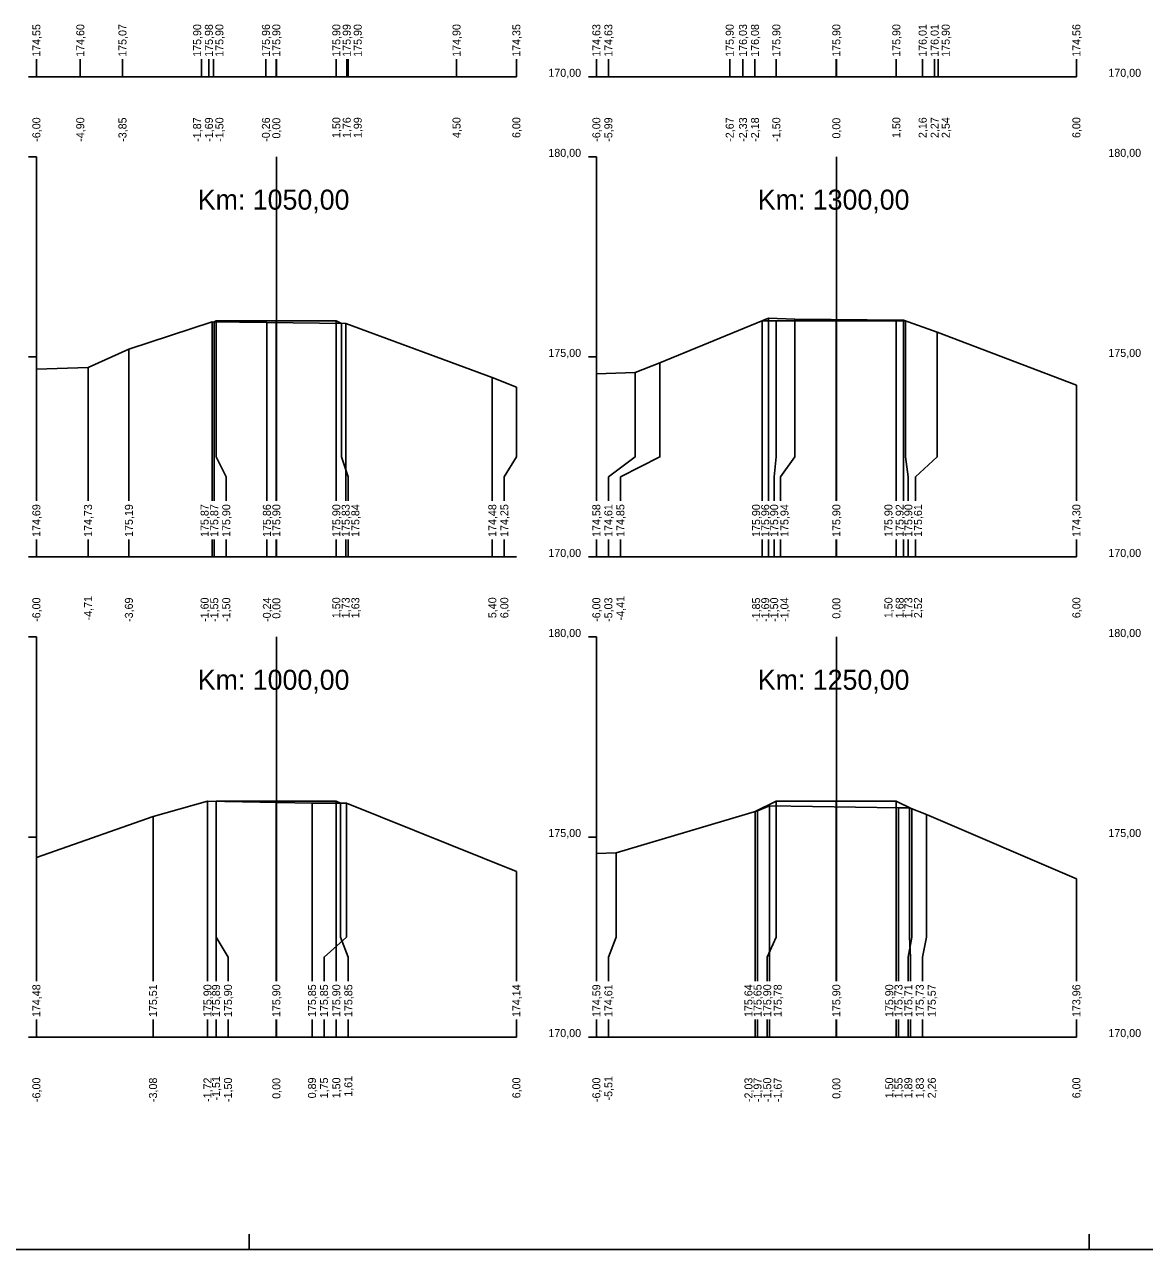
# Model space of a CAD drawing. Extents: x -614174 to -599765, y -1185887 to -1181080.
# Drawn here: x -612634.33 to -612606.33, y -1184252.54 to -1184221.93 of the extents above; entities that cross this region are included whole.
import ezdxf

# ---------------------------------------------------------------- set-up
doc = ezdxf.new("R2010")
doc.units = 0
for name, color, linetype in [('11', 7, 'Continuous'), ('16', 7, 'Continuous'), ('21', 7, 'Continuous'), ('28', 7, 'Continuous'), ('59', 7, 'Continuous'), ('8', 7, 'Continuous'), ('návrh', 7, 'Continuous')]:
    doc.layers.add(name, color=color, linetype=linetype)

msp = doc.modelspace()

# ---------------------------------------------------------------- linework, layer by layer
for points in [[(-612620.029, -1184230.656), (-612619.063, -1184230.621), (-612618.439, -1184230.382), (-612615.724, -1184229.269), (-612615.066, -1184229.29), (-612612.354, -1184229.316), (-612611.505, -1184229.619), (-612608.029, -1184230.938)], [(-612634.029, -1184230.539), (-612632.737, -1184230.499), (-612631.716, -1184230.04), (-612629.633, -1184229.36), (-612628.266, -1184229.375), (-612626.296, -1184229.399), (-612622.63, -1184230.749), (-612622.029, -1184230.988)], [(-612629.582, -1184229.361), (-612629.53, -1184229.335), (-612628.03, -1184229.335), (-612626.53, -1184229.335), (-612626.404, -1184229.398)], [(-612629.582, -1184229.361), (-612629.582, -1184229.361)], [(-612629.53, -1184229.335), (-612629.53, -1184229.335)], [(-612628.03, -1184229.335), (-612628.03, -1184229.335)], [(-612626.53, -1184229.335), (-612626.53, -1184229.335)], [(-612615.884, -1184229.335), (-612615.53, -1184229.335), (-612614.03, -1184229.335), (-612612.53, -1184229.335), (-612612.301, -1184229.335)], [(-612615.53, -1184229.335), (-612615.53, -1184229.335)], [(-612614.03, -1184229.335), (-612614.03, -1184229.335)], [(-612612.53, -1184229.335), (-612612.53, -1184229.335)], [(-612634.029, -1184242.749), (-612631.113, -1184241.724), (-612629.751, -1184241.334), (-612627.138, -1184241.388), (-612626.277, -1184241.388), (-612622.029, -1184243.095)], [(-612629.538, -1184241.339), (-612629.53, -1184241.335), (-612628.03, -1184241.335), (-612626.53, -1184241.335), (-612626.423, -1184241.388)], [(-612629.538, -1184241.339), (-612629.538, -1184241.339)], [(-612629.53, -1184241.335), (-612629.53, -1184241.335)], [(-612628.03, -1184241.335), (-612628.03, -1184241.335)], [(-612626.53, -1184241.335), (-612626.53, -1184241.335)], [(-612620.029, -1184242.645), (-612619.535, -1184242.626), (-612616, -1184241.582), (-612615.7, -1184241.458), (-612612.476, -1184241.505), (-612612.197, -1184241.508), (-612611.774, -1184241.668), (-612608.029, -1184243.276)], [(-612616.057, -1184241.598), (-612615.53, -1184241.335), (-612614.03, -1184241.335), (-612612.53, -1184241.335), (-612612.142, -1184241.529)], [(-612615.53, -1184241.335), (-612615.53, -1184241.335)], [(-612614.03, -1184241.335), (-612614.03, -1184241.335)], [(-612612.53, -1184241.335), (-612612.53, -1184241.335)], [(-612616.057, -1184241.598), (-612616.057, -1184241.598), (-612616.057, -1184241.598)]]:
    msp.add_lwpolyline(points)
at = {"layer": '11'}
for points in [[(-612634.029, -1184222.794), (-612634.029, -1184223.234)], [(-612632.931, -1184222.794), (-612632.931, -1184223.234)], [(-612631.876, -1184222.794), (-612631.876, -1184223.234)], [(-612629.899, -1184222.794), (-612629.899, -1184223.234)], [(-612629.716, -1184222.794), (-612629.716, -1184223.234)], [(-612629.599, -1184222.794), (-612629.599, -1184223.234)], [(-612628.29, -1184222.794), (-612628.29, -1184223.234)], [(-612628.03, -1184222.794), (-612628.03, -1184223.234)], [(-612626.53, -1184222.794), (-612626.53, -1184223.234)], [(-612626.27, -1184222.794), (-612626.27, -1184223.234)], [(-612626.23, -1184222.794), (-612626.23, -1184223.234)], [(-612623.525, -1184222.794), (-612623.525, -1184223.234)], [(-612622.029, -1184222.794), (-612622.029, -1184223.234)], [(-612620.029, -1184222.794), (-612620.029, -1184223.234)], [(-612619.729, -1184222.794), (-612619.729, -1184223.234)], [(-612616.695, -1184222.794), (-612616.695, -1184223.234)], [(-612616.364, -1184222.794), (-612616.364, -1184223.234)], [(-612616.064, -1184222.794), (-612616.064, -1184223.234)], [(-612615.53, -1184222.794), (-612615.53, -1184223.234)], [(-612614.03, -1184222.794), (-612614.03, -1184223.234)], [(-612612.53, -1184222.794), (-612612.53, -1184223.234)], [(-612611.872, -1184222.794), (-612611.872, -1184223.234)], [(-612611.572, -1184222.794), (-612611.572, -1184223.234)], [(-612611.488, -1184222.794), (-612611.488, -1184223.234)], [(-612608.029, -1184222.794), (-612608.029, -1184223.234)], [(-612615.724, -1184229.269), (-612615.724, -1184232.734), (-612615.724, -1184233.234), (-612615.724, -1184233.835)], [(-612615.066, -1184229.29), (-612615.066, -1184232.734), (-612615.424, -1184233.234), (-612615.424, -1184233.835)], [(-612612.354, -1184229.316), (-612612.354, -1184232.734), (-612612.354, -1184233.234), (-612612.354, -1184233.835)], [(-612629.633, -1184229.36), (-612629.633, -1184232.734), (-612629.633, -1184233.234), (-612629.633, -1184233.835)], [(-612629.582, -1184229.361), (-612629.582, -1184232.734), (-612629.582, -1184233.234), (-612629.582, -1184233.835)], [(-612629.53, -1184229.335), (-612629.53, -1184232.734), (-612629.282, -1184233.234), (-612629.282, -1184233.835)], [(-612628.266, -1184229.375), (-612628.266, -1184232.734), (-612628.266, -1184233.234), (-612628.266, -1184233.835)], [(-612628.03, -1184229.335), (-612628.03, -1184232.734), (-612628.03, -1184233.234), (-612628.03, -1184233.835)], [(-612626.53, -1184229.335), (-612626.53, -1184232.734), (-612626.53, -1184233.234), (-612626.53, -1184233.835)], [(-612626.404, -1184229.398), (-612626.404, -1184232.734), (-612626.23, -1184233.234), (-612626.23, -1184233.835)], [(-612626.296, -1184229.399), (-612626.296, -1184232.734), (-612626.296, -1184233.234), (-612626.296, -1184233.835)], [(-612615.884, -1184229.335), (-612615.884, -1184232.734), (-612615.884, -1184233.234), (-612615.884, -1184233.835)], [(-612615.53, -1184229.335), (-612615.53, -1184232.734), (-612615.584, -1184233.234), (-612615.584, -1184233.835)], [(-612614.03, -1184229.335), (-612614.03, -1184232.734), (-612614.03, -1184233.234), (-612614.03, -1184233.835)], [(-612612.53, -1184229.335), (-612612.53, -1184232.734), (-612612.53, -1184233.234), (-612612.53, -1184233.835)], [(-612612.301, -1184229.335), (-612612.301, -1184232.734), (-612612.23, -1184233.234), (-612612.23, -1184233.835)], [(-612611.505, -1184229.619), (-612611.505, -1184232.734), (-612612.054, -1184233.234), (-612612.054, -1184233.835)], [(-612631.716, -1184230.04), (-612631.716, -1184232.734), (-612631.716, -1184233.234), (-612631.716, -1184233.835)], [(-612634.029, -1184230.539), (-612634.029, -1184232.734), (-612634.029, -1184233.234), (-612634.029, -1184233.835)], [(-612632.737, -1184230.499), (-612632.737, -1184232.734), (-612632.737, -1184233.234), (-612632.737, -1184233.835)], [(-612618.439, -1184230.382), (-612618.439, -1184232.734), (-612619.429, -1184233.234), (-612619.429, -1184233.835)], [(-612622.63, -1184230.749), (-612622.63, -1184232.734), (-612622.63, -1184233.234), (-612622.63, -1184233.835)], [(-612620.029, -1184230.656), (-612620.029, -1184232.734), (-612620.029, -1184233.234), (-612620.029, -1184233.835)], [(-612619.063, -1184230.621), (-612619.063, -1184232.734), (-612619.729, -1184233.234), (-612619.729, -1184233.835)], [(-612622.029, -1184230.988), (-612622.029, -1184232.734), (-612622.33, -1184233.234), (-612622.33, -1184233.835)], [(-612608.029, -1184230.938), (-612608.029, -1184232.734), (-612608.029, -1184233.234), (-612608.029, -1184233.835)], [(-612634.029, -1184234.794), (-612634.029, -1184235.234)], [(-612632.737, -1184234.794), (-612632.737, -1184235.234)], [(-612631.716, -1184234.794), (-612631.716, -1184235.234)], [(-612629.633, -1184234.794), (-612629.633, -1184235.234)], [(-612629.582, -1184234.794), (-612629.582, -1184235.234)], [(-612629.282, -1184234.794), (-612629.282, -1184235.234)], [(-612628.266, -1184234.794), (-612628.266, -1184235.234)], [(-612628.03, -1184234.794), (-612628.03, -1184235.234)], [(-612626.53, -1184234.794), (-612626.53, -1184235.234)], [(-612626.296, -1184234.794), (-612626.296, -1184235.234)], [(-612626.23, -1184234.794), (-612626.23, -1184235.234)], [(-612622.63, -1184234.794), (-612622.63, -1184235.234)], [(-612622.33, -1184234.794), (-612622.33, -1184235.234)], [(-612620.029, -1184234.794), (-612620.029, -1184235.234)], [(-612619.729, -1184234.794), (-612619.729, -1184235.234)], [(-612619.429, -1184234.794), (-612619.429, -1184235.234)], [(-612615.884, -1184234.794), (-612615.884, -1184235.234)], [(-612615.724, -1184234.794), (-612615.724, -1184235.234)], [(-612615.584, -1184234.794), (-612615.584, -1184235.234)], [(-612615.424, -1184234.794), (-612615.424, -1184235.234)], [(-612614.03, -1184234.794), (-612614.03, -1184235.234)], [(-612612.53, -1184234.794), (-612612.53, -1184235.234)], [(-612612.354, -1184234.794), (-612612.354, -1184235.234)], [(-612612.23, -1184234.794), (-612612.23, -1184235.234)], [(-612612.054, -1184234.794), (-612612.054, -1184235.234)], [(-612608.029, -1184234.794), (-612608.029, -1184235.234)], [(-612629.751, -1184241.334), (-612629.751, -1184244.734), (-612629.751, -1184245.234), (-612629.751, -1184245.835)], [(-612629.538, -1184241.339), (-612629.538, -1184244.734), (-612629.538, -1184245.234), (-612629.538, -1184245.835)], [(-612629.53, -1184241.335), (-612629.53, -1184244.734), (-612629.238, -1184245.234), (-612629.238, -1184245.835)], [(-612628.03, -1184241.335), (-612628.03, -1184244.734), (-612628.03, -1184245.234), (-612628.03, -1184245.835)], [(-612627.138, -1184241.388), (-612627.138, -1184244.734), (-612627.138, -1184245.234), (-612627.138, -1184245.835)], [(-612626.277, -1184241.388), (-612626.277, -1184244.734), (-612626.838, -1184245.234), (-612626.838, -1184245.835)], [(-612626.53, -1184241.335), (-612626.53, -1184244.734), (-612626.53, -1184245.234), (-612626.53, -1184245.835)], [(-612626.423, -1184241.388), (-612626.423, -1184244.734), (-612626.23, -1184245.234), (-612626.23, -1184245.835)], [(-612615.53, -1184241.335), (-612615.53, -1184244.734), (-612615.757, -1184245.234), (-612615.757, -1184245.835)], [(-612615.7, -1184241.458), (-612615.7, -1184244.734), (-612615.7, -1184245.234), (-612615.7, -1184245.835)], [(-612614.03, -1184241.335), (-612614.03, -1184244.734), (-612614.03, -1184245.234), (-612614.03, -1184245.835)], [(-612612.53, -1184241.335), (-612612.53, -1184244.734), (-612612.53, -1184245.234), (-612612.53, -1184245.835)], [(-612612.476, -1184241.505), (-612612.476, -1184244.734), (-612612.476, -1184245.234), (-612612.476, -1184245.835)], [(-612612.142, -1184241.529), (-612612.142, -1184244.734), (-612612.23, -1184245.234), (-612612.23, -1184245.835)], [(-612612.197, -1184241.508), (-612612.197, -1184244.734), (-612612.176, -1184245.234), (-612612.176, -1184245.835)], [(-612631.113, -1184241.724), (-612631.113, -1184244.734), (-612631.113, -1184245.234), (-612631.113, -1184245.835)], [(-612616.057, -1184241.598), (-612616.057, -1184244.734), (-612616.057, -1184245.234), (-612616.057, -1184245.835)], [(-612616, -1184241.582), (-612616, -1184244.734), (-612616, -1184245.234), (-612616, -1184245.835)], [(-612611.774, -1184241.668), (-612611.774, -1184244.734), (-612611.876, -1184245.234), (-612611.876, -1184245.835)], [(-612634.029, -1184242.749), (-612634.029, -1184244.734), (-612634.029, -1184245.234), (-612634.029, -1184245.835)], [(-612620.029, -1184242.645), (-612620.029, -1184244.734), (-612620.029, -1184245.234), (-612620.029, -1184245.835)], [(-612619.535, -1184242.626), (-612619.535, -1184244.734), (-612619.729, -1184245.234), (-612619.729, -1184245.835)], [(-612622.029, -1184243.095), (-612622.029, -1184244.734), (-612622.029, -1184245.234), (-612622.029, -1184245.835)], [(-612608.029, -1184243.276), (-612608.029, -1184244.734), (-612608.029, -1184245.234), (-612608.029, -1184245.835)], [(-612634.029, -1184246.794), (-612634.029, -1184247.234)], [(-612631.113, -1184246.794), (-612631.113, -1184247.234)], [(-612629.751, -1184246.794), (-612629.751, -1184247.234)], [(-612629.538, -1184246.794), (-612629.538, -1184247.234)], [(-612629.238, -1184246.794), (-612629.238, -1184247.234)], [(-612628.03, -1184246.794), (-612628.03, -1184247.234)], [(-612627.138, -1184246.794), (-612627.138, -1184247.234)], [(-612626.838, -1184246.794), (-612626.838, -1184247.234)], [(-612626.53, -1184246.794), (-612626.53, -1184247.234)], [(-612626.23, -1184246.794), (-612626.23, -1184247.234)], [(-612622.029, -1184246.794), (-612622.029, -1184247.234)], [(-612620.029, -1184246.794), (-612620.029, -1184247.234)], [(-612619.729, -1184246.794), (-612619.729, -1184247.234)], [(-612616.057, -1184246.794), (-612616.057, -1184247.234)], [(-612616, -1184246.794), (-612616, -1184247.234)], [(-612615.757, -1184246.794), (-612615.757, -1184247.234)], [(-612615.7, -1184246.794), (-612615.7, -1184247.234)], [(-612614.03, -1184246.794), (-612614.03, -1184247.234)], [(-612612.53, -1184246.794), (-612612.53, -1184247.234)], [(-612612.476, -1184246.794), (-612612.476, -1184247.234)], [(-612612.23, -1184246.794), (-612612.23, -1184247.234)], [(-612612.176, -1184246.794), (-612612.176, -1184247.234)], [(-612611.876, -1184246.794), (-612611.876, -1184247.234)], [(-612608.029, -1184246.794), (-612608.029, -1184247.234)]]:
    msp.add_lwpolyline(points, dxfattribs=at)
at = {"layer": '16'}
for p, q in [((-612634.029, -1184223.234), (-612622.029, -1184223.234)), ((-612620.029, -1184223.234), (-612608.029, -1184223.234)), ((-612634.029, -1184235.234), (-612622.029, -1184235.234)), ((-612620.029, -1184235.234), (-612608.029, -1184235.234)), ((-612634.029, -1184247.234), (-612622.029, -1184247.234)), ((-612620.029, -1184247.234), (-612608.029, -1184247.234))]:
    msp.add_line(p, q, dxfattribs=at)
for points in [[(-612626.403, -1184229.398), (-612626.404, -1184229.398), (-612626.404, -1184229.398)], [(-612612.301, -1184229.335), (-612612.301, -1184229.335), (-612612.301, -1184229.335)], [(-612626.423, -1184241.388), (-612626.423, -1184241.388), (-612626.423, -1184241.388)], [(-612612.142, -1184241.529), (-612612.142, -1184241.529), (-612612.142, -1184241.529)]]:
    msp.add_lwpolyline(points, dxfattribs=at)
at = {"layer": '21'}
for p, q in [((-612634.229, -1184223.234), (-612634.029, -1184223.234)), ((-612620.229, -1184223.234), (-612620.029, -1184223.234)), ((-612634.229, -1184225.234), (-612634.029, -1184225.234)), ((-612620.229, -1184225.234), (-612620.029, -1184225.234)), ((-612634.229, -1184230.234), (-612634.029, -1184230.234)), ((-612620.229, -1184230.234), (-612620.029, -1184230.234)), ((-612634.229, -1184235.234), (-612634.029, -1184235.234)), ((-612620.229, -1184235.234), (-612620.029, -1184235.234)), ((-612634.229, -1184237.234), (-612634.029, -1184237.234)), ((-612620.229, -1184237.234), (-612620.029, -1184237.234)), ((-612634.229, -1184242.234), (-612634.029, -1184242.234)), ((-612620.229, -1184242.234), (-612620.029, -1184242.234)), ((-612634.229, -1184247.234), (-612634.029, -1184247.234)), ((-612620.229, -1184247.234), (-612620.029, -1184247.234))]:
    msp.add_line(p, q, dxfattribs=at)
at = {"layer": '28'}
for p, q in [((-612628.029, -1184223.234), (-612628.029, -1184222.794)), ((-612614.029, -1184223.234), (-612614.029, -1184222.794)), ((-612628.029, -1184233.835), (-612628.029, -1184225.234)), ((-612614.029, -1184233.835), (-612614.029, -1184225.234)), ((-612628.029, -1184235.234), (-612628.029, -1184234.794)), ((-612614.029, -1184235.234), (-612614.029, -1184234.794)), ((-612628.029, -1184245.835), (-612628.029, -1184237.234)), ((-612614.029, -1184245.835), (-612614.029, -1184237.234)), ((-612628.029, -1184247.234), (-612628.029, -1184246.794)), ((-612614.029, -1184247.234), (-612614.029, -1184246.794))]:
    msp.add_line(p, q, dxfattribs=at)
at = {"layer": '8'}
for p, q in [((-612634.029, -1184223.234), (-612634.029, -1184222.794)), ((-612620.029, -1184223.234), (-612620.029, -1184222.794)), ((-612634.029, -1184233.835), (-612634.029, -1184225.234)), ((-612620.029, -1184233.835), (-612620.029, -1184225.234)), ((-612634.029, -1184235.234), (-612634.029, -1184234.794)), ((-612620.029, -1184235.234), (-612620.029, -1184234.794)), ((-612634.029, -1184245.835), (-612634.029, -1184237.234)), ((-612620.029, -1184245.835), (-612620.029, -1184237.234)), ((-612634.029, -1184247.234), (-612634.029, -1184246.794)), ((-612620.029, -1184247.234), (-612620.029, -1184246.794))]:
    msp.add_line(p, q, dxfattribs=at)
at = {"layer": 'návrh'}
for p, q in [((-612628.713, -1184252.543), (-612628.713, -1184252.163)), ((-612607.713, -1184252.543), (-612607.713, -1184252.163)), ((-612649.713, -1184252.543), (-612628.713, -1184252.543)), ((-612628.713, -1184252.543), (-612607.713, -1184252.543)), ((-612607.713, -1184252.543), (-612586.713, -1184252.543))]:
    msp.add_line(p, q, dxfattribs=at)

# ---------------------------------------------------------------- texts
for p in [(-612629.582, -1184229.361), (-612615.885, -1184229.335), (-612629.539, -1184241.339)]:
    msp.add_text('+', height=0.001).set_placement(p)
at = {"layer": '16'}
for s, p in [('174,55', (-612633.929, -1184222.734)), ('174,60', (-612632.831, -1184222.734)), ('175,07', (-612631.776, -1184222.734)), ('175,90', (-612629.909, -1184222.734)), ('175,98', (-612629.616, -1184222.734)), ('175,90', (-612629.353, -1184222.734)), ('175,96', (-612628.19, -1184222.734)), ('175,90', (-612627.93, -1184222.734)), ('175,90', (-612626.43, -1184222.734)), ('175,99', (-612626.17, -1184222.734)), ('175,90', (-612625.895, -1184222.734)), ('174,90', (-612623.425, -1184222.734)), ('174,35', (-612621.929, -1184222.734)), ('174,63', (-612619.929, -1184222.734)), ('174,63', (-612619.629, -1184222.734)), ('175,90', (-612616.595, -1184222.734)), ('176,03', (-612616.264, -1184222.734)), ('176,08', (-612615.964, -1184222.734)), ('175,90', (-612615.43, -1184222.734)), ('175,90', (-612613.93, -1184222.734)), ('175,90', (-612612.43, -1184222.734)), ('176,01', (-612611.772, -1184222.734)), ('176,01', (-612611.472, -1184222.734)), ('175,90', (-612611.195, -1184222.734)), ('174,56', (-612607.929, -1184222.734)), ('174,69', (-612633.929, -1184234.734)), ('174,73', (-612632.637, -1184234.734)), ('175,19', (-612631.616, -1184234.734)), ('175,87', (-612629.723, -1184234.734)), ('175,87', (-612629.482, -1184234.734)), ('175,90', (-612629.182, -1184234.734)), ('175,86', (-612628.166, -1184234.734)), ('175,90', (-612627.93, -1184234.734)), ('175,90', (-612626.43, -1184234.734)), ('175,83', (-612626.196, -1184234.734)), ('175,84', (-612625.954, -1184234.734)), ('174,48', (-612622.53, -1184234.734)), ('174,25', (-612622.23, -1184234.734)), ('174,58', (-612619.929, -1184234.734)), ('174,61', (-612619.629, -1184234.734)), ('174,85', (-612619.329, -1184234.734)), ('175,90', (-612615.936, -1184234.734)), ('175,96', (-612615.707, -1184234.734)), ('175,90', (-612615.484, -1184234.734)), ('175,94', (-612615.227, -1184234.734)), ('175,90', (-612613.93, -1184234.734)), ('175,90', (-612612.627, -1184234.734)), ('175,92', (-612612.347, -1184234.734)), ('175,90', (-612612.13, -1184234.734)), ('175,61', (-612611.888, -1184234.734)), ('174,30', (-612607.929, -1184234.734)), ('174,48', (-612633.929, -1184246.734)), ('175,51', (-612631.013, -1184246.734)), ('175,90', (-612629.651, -1184246.734)), ('175,89', (-612629.438, -1184246.734)), ('175,90', (-612629.138, -1184246.734)), ('175,90', (-612627.93, -1184246.734)), ('175,85', (-612627.038, -1184246.734)), ('175,85', (-612626.738, -1184246.734)), ('175,90', (-612626.43, -1184246.734)), ('175,85', (-612626.13, -1184246.734)), ('174,14', (-612621.929, -1184246.734)), ('174,59', (-612619.929, -1184246.734)), ('174,61', (-612619.629, -1184246.734)), ('175,64', (-612616.127, -1184246.734)), ('175,65', (-612615.9, -1184246.734)), ('175,90', (-612615.657, -1184246.734)), ('175,78', (-612615.396, -1184246.734)), ('175,90', (-612613.93, -1184246.734)), ('175,90', (-612612.606, -1184246.734)), ('175,73', (-612612.376, -1184246.734)), ('175,71', (-612612.13, -1184246.734)), ('175,73', (-612611.844, -1184246.734)), ('175,57', (-612611.544, -1184246.734)), ('173,96', (-612607.929, -1184246.734))]:
    msp.add_text(s, height=0.2, rotation=90, dxfattribs=at).set_placement(p)
at = {"layer": '21'}
for s, p in [('170,00', (-612621.229, -1184223.234)), ('170,00', (-612607.229, -1184223.234)), ('180,00', (-612621.229, -1184225.234)), ('180,00', (-612607.229, -1184225.234)), ('175,00', (-612621.229, -1184230.234)), ('175,00', (-612607.229, -1184230.234)), ('170,00', (-612621.229, -1184235.234)), ('170,00', (-612607.229, -1184235.234)), ('180,00', (-612621.229, -1184237.234)), ('180,00', (-612607.229, -1184237.234)), ('175,00', (-612621.229, -1184242.234)), ('175,00', (-612607.229, -1184242.234)), ('170,00', (-612621.229, -1184247.234)), ('170,00', (-612607.229, -1184247.234))]:
    msp.add_text(s, height=0.2, dxfattribs=at).set_placement(p)
at = {"layer": '28'}
for s, p in [('Km: 1050,00', (-612629.993, -1184226.554)), ('Km: 1300,00', (-612615.993, -1184226.554)), ('Km: 1000,00', (-612629.993, -1184238.554)), ('Km: 1250,00', (-612615.993, -1184238.554))]:
    msp.add_text(s, height=0.5, dxfattribs=at).set_placement(p)
at = {"layer": '59'}
for s, p in [('-6,00', (-612633.929, -1184224.857)), ('-4,90', (-612632.831, -1184224.857)), ('-3,85', (-612631.776, -1184224.859)), ('-1,87', (-612629.909, -1184224.858)), ('-1,69', (-612629.616, -1184224.858)), ('-1,50', (-612629.353, -1184224.857)), ('-0,26', (-612628.19, -1184224.858)), ('0,00', (-612627.93, -1184224.777)), ('1,50', (-612626.43, -1184224.764)), ('1,76', (-612626.17, -1184224.765)), ('1,99', (-612625.895, -1184224.765)), ('4,50', (-612623.425, -1184224.764)), ('6,00', (-612621.929, -1184224.764)), ('-6,00', (-612619.929, -1184224.857)), ('-5,99', (-612619.629, -1184224.858)), ('-2,67', (-612616.595, -1184224.858)), ('-2,33', (-612616.264, -1184224.858)), ('-2,18', (-612615.964, -1184224.858)), ('-1,50', (-612615.43, -1184224.857)), ('0,00', (-612613.93, -1184224.777)), ('1,50', (-612612.43, -1184224.764)), ('2,16', (-612611.772, -1184224.765)), ('2,27', (-612611.472, -1184224.765)), ('2,54', (-612611.195, -1184224.764)), ('6,00', (-612607.929, -1184224.764)), ('-6,00', (-612633.929, -1184236.857)), ('-4,71', (-612632.637, -1184236.819)), ('-3,69', (-612631.616, -1184236.858)), ('-1,60', (-612629.723, -1184236.857)), ('-1,55', (-612629.482, -1184236.859)), ('-1,50', (-612629.182, -1184236.857)), ('-0,24', (-612628.166, -1184236.857)), ('0,00', (-612627.93, -1184236.777)), ('1,50', (-612626.43, -1184236.764)), ('1,73', (-612626.196, -1184236.765)), ('1,63', (-612625.954, -1184236.765)), ('5,40', (-612622.53, -1184236.764)), ('6,00', (-612622.23, -1184236.764)), ('-6,00', (-612619.929, -1184236.857)), ('-5,03', (-612619.629, -1184236.858)), ('-4,41', (-612619.329, -1184236.819)), ('-1,85', (-612615.936, -1184236.859)), ('-1,69', (-612615.707, -1184236.858)), ('-1,50', (-612615.484, -1184236.857)), ('-1,04', (-612615.227, -1184236.857)), ('0,00', (-612613.93, -1184236.777)), ('1,50', (-612612.627, -1184236.764)), ('1,68', (-612612.347, -1184236.765)), ('1,73', (-612612.13, -1184236.765)), ('2,52', (-612611.888, -1184236.763)), ('6,00', (-612607.929, -1184236.764)), ('-6,00', (-612633.929, -1184248.857)), ('-3,08', (-612631.013, -1184248.858)), ('-1,72', (-612629.651, -1184248.856)), ('-1,51', (-612629.438, -1184248.819)), ('-1,50', (-612629.138, -1184248.857)), ('0,00', (-612627.93, -1184248.777)), ('0,89', (-612627.038, -1184248.765)), ('1,75', (-612626.738, -1184248.766)), ('1,50', (-612626.43, -1184248.764)), ('1,61', (-612626.13, -1184248.726)), ('6,00', (-612621.929, -1184248.764)), ('-6,00', (-612619.929, -1184248.857)), ('-5,51', (-612619.629, -1184248.819)), ('-2,03', (-612616.127, -1184248.858)), ('-1,97', (-612615.9, -1184248.858)), ('-1,50', (-612615.657, -1184248.857)), ('-1,67', (-612615.396, -1184248.858)), ('0,00', (-612613.93, -1184248.777)), ('1,50', (-612612.606, -1184248.764)), ('1,55', (-612612.376, -1184248.766)), ('1,89', (-612612.13, -1184248.765)), ('1,83', (-612611.844, -1184248.765)), ('2,26', (-612611.544, -1184248.765)), ('6,00', (-612607.929, -1184248.764))]:
    msp.add_text(s, height=0.2, rotation=90, dxfattribs=at).set_placement(p)

doc.saveas('drawing.dxf')
